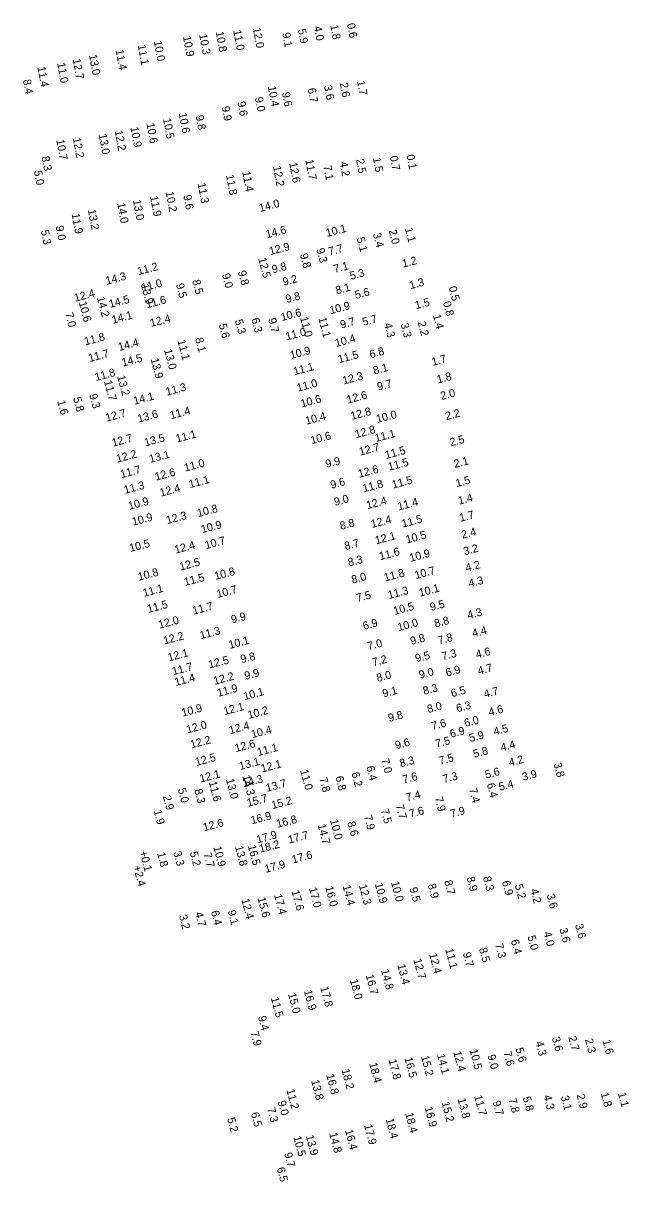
# Model space of a CAD drawing. Extents: x 815385 to 820851, y 582449 to 604245.
# Drawn here: x 816474 to 816853, y 597646 to 598369 of the extents above; entities that cross this region are included whole.
import ezdxf

# ---------------------------------------------------------------- set-up
doc = ezdxf.new("R2010")
doc.units = 0
doc.layers.add('V-TOPO-SOUN-021909', color=7, linetype='Continuous')
doc.layers.add('V-TOPO-SOUN-EXCSS', color=7, linetype='Continuous')

msp = doc.modelspace()

# ---------------------------------------------------------------- texts
at = {"layer": 'V-TOPO-SOUN-021909'}
for s, rotation, p in [('1.8', 280.549, (816666.18, 598368.06)), ('0.6', 280.549, (816676.66, 598369.01)), ('10.9 ', 280.549, (816574.11, 598361.01)), ('10.3 ', 280.549, (816584.21, 598362.31)), ('10.8 ', 280.549, (816594.57, 598363.89)), ('11.0 ', 280.549, (816605.57, 598364.85)), ('12.0 ', 280.549, (816617.78, 598366.31)), ('9.1', 280.549, (816636.13, 598363.21)), ('5.9', 280.549, (816645.93, 598365.51)), ('4.0', 280.549, (816655.88, 598367.26)), ('11.1 ', 280.549, (816545.8, 598355.68)), ('10.0 ', 280.549, (816555.87, 598358.12)), ('12.7 ', 280.549, (816505.13, 598346.92)), ('13.0 ', 280.549, (816515.33, 598349.48)), ('11.4 ', 280.549, (816532, 598352.66)), ('11.4 ', 280.549, (816483.1, 598342.01)), ('11.0 ', 280.549, (816495.43, 598344.46)), ('8.4', 280.549, (816474.07, 598333.95)), ('2.6', 280.549, (816672.19, 598331.91)), ('1.7', 280.549, (816682.9, 598333.22)), ('10.4 ', 280.549, (816627.18, 598329.82)), ('9.6', 280.549, (816635.99, 598326.05)), ('6.7', 280.549, (816652.08, 598328.55)), ('3.6', 280.549, (816662.25, 598330.33)), ('9.9', 280.549, (816598.25, 598317.16)), ('9.6', 280.549, (816608.12, 598320.21)), ('9.0', 280.549, (816619.08, 598322.96)), ('10.6 ', 280.549, (816571.41, 598313.09)), ('9.8', 280.549, (816581.95, 598311.58)), ('10.9 ', 280.549, (816541.24, 598304.36)), ('10.6 ', 280.549, (816551.28, 598306.75)), ('10.5 ', 280.549, (816561.63, 598309.67)), ('10.7 ', 280.549, (816494.87, 598296.48)), ('12.2 ', 280.549, (816505.23, 598297.6)), ('13.0 ', 280.549, (816521.37, 598299.93)), ('12.2 ', 280.549, (816531.43, 598302.16)), ('8.3', 280.549, (816485.65, 598286)), ('12.6 ', 280.549, (816640.49, 598282.15)), ('11.7 ', 280.549, (816650.59, 598283.99)), ('4.2', 280.549, (816672.08, 598282.57)), ('2.5', 280.549, (816682.33, 598284.38)), ('1.5', 280.549, (816692.86, 598285.2)), ('0.7', 280.549, (816703.43, 598286.21)), ('0.1', 280.549, (816713.86, 598287.01)), ('5.0', 280.549, (816480.95, 598277.06)), ('11.8 ', 280.549, (816600.96, 598274.52)), ('11.4 ', 280.549, (816611.17, 598276.64)), ('12.2 ', 280.549, (816630.39, 598279.91)), ('7.1', 280.549, (816661.88, 598280.23)), ('11.3 ', 280.549, (816583.26, 598269.33)), ('11.9 ', 280.549, (816553.51, 598261.21)), ('10.2 ', 280.549, (816563.26, 598263.98)), ('9.6', 280.549, (816574.33, 598261.78)), ('14.0 ', 14.724, (816622.35, 598251.54)), ('13.2 ', 280.549, (816514.66, 598252.78)), ('14.0 ', 280.549, (816532.98, 598256.95)), ('13.0 ', 280.549, (816542.8, 598258.85)), ('11.9 ', 280.549, (816504.5, 598250.3)), ('5.3', 280.549, (816485.31, 598239.92)), ('9.0', 280.549, (816494.5, 598242.59)), ('14.6 ', 14.724, (816626.57, 598235.07)), ('10.1 ', 14.724, (816664.12, 598235.94)), ('3.4', 284.724, (816692.79, 598237.88)), ('2.0', 284.724, (816702.67, 598239.95)), ('1.1', 284.724, (816712.79, 598241.12)), ('12.9 ', 14.724, (816628.7, 598224.58)), ('7.7', 14.724, (816665.6, 598224.35)), ('5.1', 284.724, (816682.66, 598235.18)), ('9.8', 284.724, (816647.19, 598225.01)), ('9.3', 284.724, (816657.46, 598228.34)), ('1.2', 14.724, (816711.77, 598216.76)), ('11.2 ', 14.724, (816546.31, 598212.07)), ('12.5 ', 284.724, (816621.12, 598222.45)), ('9.8', 14.724, (816630.38, 598213.16)), ('7.1', 14.724, (816669.04, 598213.43)), ('5.3', 14.724, (816679.09, 598209.12)), ('14.3 ', 14.724, (816526.45, 598206.05)), ('11.0 ', 14.724, (816548.84, 598201.77)), ('8.5', 284.724, (816579.87, 598208.66)), ('9.0', 284.724, (816598.48, 598212.53)), ('9.8', 284.724, (816608.46, 598214.26)), ('9.2', 14.724, (816637.16, 598205.39)), ('1.3', 14.724, (816716.3, 598203.26)), ('12.4 ', 14.724, (816506.78, 598195.44)), ('9.5', 284.724, (816569.68, 598206.35)), ('9.8', 14.724, (816638.97, 598194.64)), ('8.1', 14.724, (816670.23, 598200.08)), ('5.6', 14.724, (816682.24, 598197.2)), ('0.5', 284.724, (816740.18, 598204.52)), ('10.6 ', 284.724, (816508.95, 598195.04)), ('14.2 ', 284.724, (816520.21, 598198.07)), ('14.5 ', 14.724, (816528.53, 598191.62)), ('11.6 ', 14.724, (816551.48, 598191.35)), ('10.9 ', 14.724, (816666.38, 598187.64)), ('1.5', 14.724, (816719.82, 598190.78)), ('0.8', 284.724, (816736.58, 598195.08)), ('7.0', 284.724, (816500.41, 598188.14)), ('14.1 ', 14.724, (816530.35, 598181.72)), ('12.4 ', 14.724, (816554.2, 598179.69)), ('10.6 ', 14.724, (816635.96, 598183.37)), ('5.7', 14.724, (816686.92, 598180.33)), ('1.4', 284.724, (816730.35, 598187.02)), ('5.6', 284.724, (816596.42, 598181.18)), ('5.3', 284.724, (816606.52, 598183.83)), ('6.3', 284.724, (816616.81, 598184.74)), ('9.7', 284.724, (816627.27, 598184.64)), ('11.1 ', 284.724, (816658.7, 598185.22)), ('9.7', 14.724, (816673.11, 598178.7)), ('4.3', 284.724, (816699.8, 598181.66)), ('3.3', 284.724, (816710.08, 598181.58)), ('2.2', 284.724, (816720.84, 598182.62)), ('11.8 ', 14.724, (816513.1, 598168.23)), ('14.4 ', 14.724, (816534.3, 598164.71)), ('8.1', 284.724, (816581.7, 598172.48)), ('11.0 ', 14.724, (816638.94, 598171.31)), ('10.4 ', 14.724, (816669.85, 598167.22)), ('11.7 ', 14.724, (816515.67, 598157.81)), ('13.0 ', 284.724, (816562.28, 598165.29)), ('11.1 ', 284.724, (816570.63, 598171.12)), ('10.9 ', 14.724, (816641.71, 598159.65)), ('6.8', 14.724, (816691.41, 598160.14)), ('14.5 ', 14.724, (816536.52, 598154.95)), ('13.9 ', 284.724, (816553.88, 598159.64)), ('11.5 ', 14.724, (816671.73, 598157.06)), ('1.7', 14.724, (816730.24, 598155.44)), ('11.8 ', 14.724, (816519.63, 598145.93)), ('11.1 ', 14.724, (816643.79, 598149.56)), ('12.3 ', 14.724, (816674.54, 598143.76)), ('8.1', 14.724, (816693.72, 598150.02)), ('1.8', 14.724, (816733.54, 598144.39)), ('11.7 ', 284.724, (816524.74, 598145.76)), ('13.2 ', 284.724, (816532.96, 598148.86)), ('11.3 ', 14.724, (816564.01, 598136.8)), ('11.0 ', 14.724, (816645.98, 598139.29)), ('9.7', 14.724, (816696.23, 598139.95)), ('9.3', 284.724, (816515.5, 598137.37)), ('14.1 ', 14.724, (816543.81, 598131.12)), ('10.6 ', 14.724, (816648.42, 598129.42)), ('12.6 ', 14.724, (816677.16, 598131.82)), ('2.0', 14.724, (816735.77, 598134.14)), ('1.6', 284.724, (816495.5, 598133.38)), ('5.8', 284.724, (816505.43, 598135.32)), ('11.4 ', 14.724, (816566.61, 598122.11)), ('12.8 ', 14.724, (816679.57, 598121.64)), ('12.7 ', 14.724, (816526.35, 598120.55)), ('13.6 ', 14.724, (816546.39, 598120.02)), ('10.4 ', 14.724, (816651.29, 598118.67)), ('10.0 ', 14.724, (816695.59, 598119.71)), ('2.2', 14.724, (816738.79, 598121.5)), ('11.1 ', 14.724, (816570.33, 598107.49)), ('12.8 ', 14.724, (816682.26, 598110.27)), ('11.1 ', 14.724, (816694.69, 598107.85)), ('12.7 ', 14.724, (816530.32, 598104.94)), ('13.5 ', 14.724, (816550.62, 598105.11)), ('10.6 ', 14.724, (816654.56, 598106.44)), ('12.7 ', 14.724, (816684.91, 598099.37)), ('2.5', 14.724, (816741.55, 598105.14)), ('12.2 ', 14.724, (816533.09, 598095.02)), ('13.1 ', 14.724, (816553.65, 598094.85)), ('11.5 ', 14.724, (816701.1, 598097.28)), ('11.7 ', 14.724, (816535.64, 598085.28)), ('11.0 ', 14.724, (816575.5, 598089.37)), ('9.9', 14.724, (816663.89, 598091.64)), ('12.6 ', 14.724, (816684.24, 598085.55)), ('11.5 ', 14.724, (816702.99, 598089.88)), ('2.1', 14.724, (816744.13, 598091.65)), ('12.6 ', 14.724, (816557.23, 598083.72)), ('11.1 ', 14.724, (816578.46, 598079.07)), ('9.6', 14.724, (816666.94, 598078.66)), ('11.5 ', 14.724, (816705.46, 598078.77)), ('1.5', 14.724, (816745.22, 598079.65)), ('11.3 ', 14.724, (816537.87, 598075.5)), ('12.4 ', 14.724, (816560.3, 598073.74)), ('11.8 ', 14.724, (816687.12, 598076.39)), ('10.9 ', 14.724, (816540.6, 598065.53)), ('9.0', 14.724, (816669.24, 598067.94)), ('12.4 ', 14.724, (816689.38, 598065.9)), ('11.4 ', 14.724, (816708.99, 598065.12)), ('1.4', 14.724, (816746.8, 598068.73)), ('12.3 ', 14.724, (816564.27, 598056.62)), ('10.8 ', 14.724, (816583.69, 598060.98)), ('1.7', 14.724, (816747.56, 598058.02)), ('10.9 ', 14.724, (816542.98, 598055.62)), ('10.9 ', 14.724, (816586.14, 598050.91)), ('8.8', 14.724, (816672.89, 598052.99)), ('12.4 ', 14.724, (816692.29, 598054.16)), ('11.5 ', 14.724, (816711.57, 598054.42)), ('12.1 ', 14.724, (816694.91, 598043.92)), ('10.5 ', 14.724, (816714.1, 598044.47)), ('2.4', 14.724, (816748.87, 598047.46)), ('10.5 ', 14.724, (816541.27, 598039.17)), ('12.4 ', 14.724, (816569.49, 598038.15)), ('10.7 ', 14.724, (816588.5, 598041.01)), ('8.7', 14.724, (816675.75, 598040.37)), ('3.2', 14.724, (816750.15, 598037.12)), ('12.5 ', 14.724, (816572.58, 598027.56)), ('8.3', 14.724, (816677.91, 598030.13)), ('11.6 ', 14.724, (816697.5, 598034.04)), ('10.9 ', 14.724, (816716.43, 598033.04)), ('10.8 ', 14.724, (816546.6, 598021.24)), ('10.8 ', 14.724, (816594.43, 598021.73)), ('11.8 ', 14.724, (816700.46, 598020.74)), ('10.7 ', 14.724, (816719.65, 598022.26)), ('4.2', 14.724, (816751.42, 598026.82)), ('11.5 ', 14.724, (816575.45, 598017.94)), ('8.0', 14.724, (816680.17, 598019.4)), ('4.3', 14.724, (816753.3, 598017.09)), ('11.1 ', 14.724, (816549.69, 598011.16)), ('10.7 ', 14.724, (816595.78, 598010.42)), ('7.5', 14.724, (816683.08, 598007.94)), ('11.3 ', 14.724, (816702.88, 598009.79)), ('10.1 ', 14.724, (816722.26, 598011.26)), ('11.5 ', 14.724, (816552.46, 598001.09)), ('11.7 ', 14.724, (816580.74, 598000.05)), ('10.5 ', 14.724, (816706.42, 597999.9)), ('9.5', 14.724, (816729.19, 598002.31)), ('12.0 ', 14.724, (816559.39, 597991.28)), ('9.9', 14.724, (816604.9, 597994.55)), ('8.8', 14.724, (816731.95, 597992.02)), ('4.3', 14.724, (816752.55, 597997.22)), ('11.3 ', 14.724, (816585.27, 597984.71)), ('6.9', 14.724, (816687.25, 597990.55)), ('10.0 ', 14.724, (816708.93, 597989.76)), ('4.4', 14.724, (816755.55, 597985.9)), ('12.2 ', 14.724, (816562.54, 597981.4)), ('10.1 ', 14.724, (816603.34, 597978.68)), ('7.0', 14.724, (816690.15, 597977.84)), ('9.8', 14.724, (816716.88, 597981.08)), ('7.8', 14.724, (816734.21, 597981.45)), ('12.1 ', 14.724, (816565.29, 597970.85)), ('9.5', 14.724, (816719.98, 597970.28)), ('7.3', 14.724, (816736.59, 597971.52)), ('4.6', 14.724, (816757.84, 597972.68)), ('11.7 ', 14.724, (816568.02, 597962.21)), ('12.5 ', 14.724, (816590.68, 597966.4)), ('9.8', 14.724, (816610.82, 597969.69)), ('7.2', 14.724, (816693.12, 597967.79)), ('12.2 ', 14.724, (816593.88, 597956.24)), ('9.9', 14.724, (816613.28, 597959.36)), ('8.0', 14.724, (816695.79, 597958.08)), ('9.0', 14.724, (816722.34, 597960.01)), ('6.9', 14.724, (816739.06, 597961.34)), ('4.7', 14.724, (816759.08, 597962.44)), ('11.9 ', 14.724, (816596.16, 597948.75)), ('8.3', 14.724, (816724.85, 597949.99)), ('6.5', 14.724, (816742.31, 597948.46)), ('10.1 ', 14.724, (816612.59, 597946.62)), ('9.1', 14.724, (816699.54, 597948.34)), ('4.7', 14.724, (816762.87, 597947.98)), ('10.9 ', 14.724, (816573.94, 597936.35)), ('12.1 ', 14.724, (816600.12, 597937.3)), ('10.2 ', 14.724, (816615.28, 597934.95)), ('8.0', 14.724, (816727.46, 597938.59)), ('6.3', 14.724, (816745.64, 597939.06)), ('4.6', 14.724, (816765.79, 597936.71)), ('12.0 ', 14.724, (816576.89, 597925.9)), ('9.8', 14.724, (816703.06, 597933.03)), ('7.6', 14.724, (816730.15, 597927.92)), ('6.0', 14.724, (816750.57, 597929.83)), ('12.4 ', 14.724, (816603.56, 597925.44)), ('10.4 ', 14.724, (816617.45, 597922.86)), ('5.9', 14.724, (816753.75, 597920.46)), ('4.5', 14.724, (816768.96, 597924.63)), ('12.2 ', 14.724, (816579.38, 597916.5)), ('12.6 ', 14.724, (816607.17, 597914.19)), ('11.1 ', 14.724, (816621.21, 597911.73)), ('9.6', 14.724, (816707.42, 597915.96)), ('7.5', 14.724, (816732.62, 597916.99)), ('4.4', 14.724, (816773.34, 597914.59)), ('12.5 ', 14.724, (816582.48, 597905.55)), ('7.5', 14.724, (816734.8, 597906.34)), ('5.8', 14.724, (816756.27, 597910.65)), ('4.2', 14.724, (816778.48, 597905.25)), ('13.1 ', 14.724, (816609.88, 597903.02)), ('12.1 ', 14.724, (816623.56, 597901.49)), ('6.4', 284.724, (816688.68, 597904.97)), ('7.0', 284.724, (816697.97, 597909.59)), ('8.3', 14.724, (816710.26, 597904.68)), ('3.8', 284.724, (816805.77, 597907.04)), ('12.1 ', 14.724, (816585.2, 597895.19)), ('13.0 ', 284.724, (816600.95, 597897.11)), ('14.3 ', 14.724, (816611.93, 597892.12)), ('11.0 ', 284.724, (816647.38, 597902.71)), ('7.8', 284.724, (816659.33, 597897.77)), ('6.8', 284.724, (816669.29, 597898.67)), ('6.2', 284.724, (816679.4, 597901.12)), ('7.6', 14.724, (816712.18, 597894.64)), ('7.3', 14.724, (816737.26, 597894.87)), ('5.6', 14.724, (816763.63, 597897.66)), ('3.9', 14.724, (816786.84, 597896.23)), ('5.0', 284.724, (816570.89, 597891.08)), ('8.3', 284.724, (816581.16, 597890.63)), ('11.6 ', 284.724, (816590.18, 597895.45)), ('13.7 ', 14.724, (816626.65, 597889.4)), ('7.4', 14.724, (816714.15, 597883.41)), ('7.4', 284.724, (816752.91, 597891.12)), ('6.4', 284.724, (816764.04, 597894.31)), ('5.4', 14.724, (816772.21, 597890.04)), ('2.9', 284.724, (816561.55, 597886.59)), ('15.7 ', 14.724, (816614.74, 597880.01)), ('15.2 ', 14.724, (816630.11, 597878.62)), ('7.9', 284.724, (816731.43, 597885.69)), ('1.9', 284.724, (816555.77, 597877.54)), ('16.9 ', 14.724, (816617.19, 597869.09)), ('7.5', 284.724, (816697.74, 597878.12)), ('7.7', 284.724, (816707.07, 597880.95)), ('7.6', 14.724, (816716.26, 597873.27)), ('7.9', 14.724, (816741.87, 597873.23)), ('12.6 ', 14.724, (816587.33, 597864.72)), ('16.8 ', 14.724, (816633.2, 597866.87)), ('14.7 ', 284.724, (816658.27, 597868.7)), ('10.0 ', 284.724, (816666.03, 597871.66)), ('8.6', 284.724, (816676.8, 597870.31)), ('7.9', 284.724, (816687.25, 597874.2)), ('17.9 ', 14.724, (816620.71, 597857.16)), ('17.7 ', 14.724, (816640.47, 597857.05)), ('10.9 ', 284.724, (816593.09, 597854.86)), ('13.8 ', 284.724, (816606.62, 597855.19)), ('16.5 ', 284.724, (816614.61, 597855.66)), ('18.2 ', 14.724, (816622.46, 597851.34)), ('+0.1 ', 284.724, (816546.86, 597852.02)), ('1.8', 284.724, (816557.91, 597851.07)), ('3.3', 284.724, (816568.07, 597851.71)), ('5.2', 284.724, (816578.32, 597851.54)), ('7.7', 284.724, (816586.9, 597850.76)), ('17.6 ', 14.724, (816642.9, 597844.64)), ('+2.4 ', 284.724, (816542.92, 597842.74)), ('17.9 ', 14.724, (816625.88, 597838.8)), ('10.0 ', 284.724, (816704.15, 597832.89)), ('8.7', 284.724, (816737.4, 597833.65)), ('8.9', 284.724, (816751.4, 597835.8)), ('8.3', 284.724, (816761.64, 597836.01)), ('6.9', 284.724, (816773.56, 597833.28)), ('17.4 ', 284.724, (816631.04, 597824.95)), ('17.6 ', 284.724, (816641.94, 597827.37)), ('17.0 ', 284.724, (816652.85, 597829.18)), ('16.0 ', 284.724, (816663.02, 597829.87)), ('14.4 ', 284.724, (816673.89, 597830.6)), ('12.3 ', 284.724, (816684.04, 597831)), ('10.9 ', 284.724, (816694.03, 597831.9)), ('9.5', 284.724, (816715.68, 597829.22)), ('8.9', 284.724, (816727.08, 597831.41)), ('5.2', 284.724, (816781.55, 597831.13)), ('4.2', 284.724, (816791.21, 597828.26)), ('3.6', 284.724, (816801.42, 597825.1)), ('12.4 ', 284.724, (816610.58, 597822.13)), ('15.6 ', 284.724, (816620.67, 597823.05)), ('3.2', 284.724, (816571.6, 597812.03)), ('4.7', 284.724, (816581.58, 597813.77)), ('6.4', 284.724, (816591.58, 597814.66)), ('9.1', 284.724, (816602.02, 597814.95)), ('3.6', 284.724, (816809.39, 597803.81)), ('3.6', 284.724, (816819.18, 597806.31)), ('6.4', 284.724, (816779.07, 597796.57)), ('5.0', 284.724, (816789.46, 597799.12)), ('4.0', 284.724, (816799.5, 597801.49)), ('11.1 ', 284.724, (816738.03, 597791.04)), ('9.7', 284.724, (816749.04, 597788.62)), ('8.5', 284.724, (816759.14, 597791.45)), ('7.3', 284.724, (816769.17, 597794.08)), ('12.7 ', 284.724, (816718.16, 597784.64)), ('12.4 ', 284.724, (816727.99, 597788.03)), ('16.7 ', 284.724, (816688.31, 597774.81)), ('14.8 ', 284.724, (816697.91, 597777.96)), ('13.4 ', 284.724, (816708.1, 597781.23)), ('17.8 ', 284.724, (816659.94, 597767.22)), ('18.0 ', 284.724, (816678.44, 597771.86)), ('11.5 ', 284.724, (816629.04, 597760.63)), ('15.0 ', 284.724, (816639.79, 597763.14)), ('16.9 ', 284.724, (816649.72, 597765.07)), ('9.4', 284.724, (816621.02, 597748.89)), ('7.9', 284.724, (816616.32, 597739.25)), ('4.3', 284.724, (816794.44, 597733.07)), ('3.6', 284.724, (816804.74, 597735.84)), ('2.7', 284.724, (816814.96, 597736.27)), ('2.3', 284.724, (816825.34, 597734.77)), ('1.6', 284.724, (816836.41, 597734)), ('15.2 ', 284.724, (816722.87, 597724.12)), ('14.1 ', 284.724, (816732.86, 597725.2)), ('12.4 ', 284.724, (816743.11, 597726.91)), ('10.5 ', 284.724, (816753.22, 597728.14)), ('9.0', 284.724, (816764.42, 597724.7)), ('7.6', 284.724, (816774.44, 597726.68)), ('5.6', 284.724, (816781.95, 597729.08)), ('18.4 ', 284.724, (816690.48, 597719.75)), ('17.8 ', 284.724, (816702.6, 597721.86)), ('16.5 ', 284.724, (816712.53, 597723.08)), ('13.8 ', 284.724, (816654.19, 597709.05)), ('16.8 ', 284.724, (816663.67, 597712.59)), ('18.2 ', 284.724, (816673.24, 597715.79)), ('11.2 ', 284.724, (816638.77, 597703.25)), ('9.0', 284.724, (816633.34, 597695.88)), ('15.2 ', 284.724, (816735.77, 597695.31)), ('13.8 ', 284.724, (816745.72, 597697.53)), ('11.7 ', 284.724, (816756.13, 597699.36)), ('9.7', 284.724, (816767.65, 597695.9)), ('7.8', 284.724, (816777.6, 597697.48)), ('5.8', 284.724, (816786.52, 597698.54)), ('4.3', 284.724, (816799.46, 597699.48)), ('3.1', 284.724, (816810.24, 597699.09)), ('2.9', 284.724, (816820.15, 597700.07)), ('1.8', 284.724, (816835.24, 597701.09)), ('1.1', 284.724, (816846.04, 597701.08)), ('6.5', 284.724, (816616.57, 597688.72)), ('7.3', 284.724, (816626.73, 597691.57)), ('18.4 ', 284.724, (816713.02, 597688.54)), ('16.9 ', 284.724, (816725.13, 597692.21)), ('5.2', 284.724, (816601.7, 597685.38)), ('17.9 ', 284.724, (816687.32, 597681.2)), ('18.4 ', 284.724, (816700.83, 597684.97)), ('10.5 ', 284.724, (816643.08, 597673.87)), ('13.9 ', 284.724, (816650.86, 597674.5)), ('14.8 ', 284.724, (816665.5, 597676)), ('16.4 ', 284.724, (816675.37, 597677.96)), ('9.7', 284.724, (816637.31, 597663.56)), ('6.5', 284.724, (816632.73, 597654.37))]:
    msp.add_text(s, height=5, rotation=rotation, dxfattribs=at).set_placement(p)
at = {"layer": 'V-TOPO-SOUN-EXCSS'}
for s, rotation, p in [('13.9 ', 284.724, (816547.8, 598206.1)), ('11.0 ', 284.724, (816647.25, 598185.56)), ('11.4 ', 14.724, (816569.56, 597955.43)), ('6.9', 14.724, (816741.7, 597923.12)), ('14.3 ', 284.724, (816611.12, 597899.29))]:
    msp.add_text(s, height=5, rotation=rotation, dxfattribs=at).set_placement(p)

doc.saveas('drawing.dxf')
